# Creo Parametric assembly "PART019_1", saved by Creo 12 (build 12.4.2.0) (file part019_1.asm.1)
Units: Custom; MM, KILOGRAM, SECS

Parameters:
  PTC_WM_ITERATION = "0"
  PTC_WM_VERSION = "-.0"
  PTC_WM_LIFECYCLE_STATE = "In Work"
  PTC_WM_LIFECYCLE = "MO_CADDocument"
  PTC_WM_CREATED_BY = "Maximilian Roepper (Z0017RMS: MO)"
  PTC_WM_CREATED_ON = "18-Sep-26 11:36:42 AM"
  PTC_WM_MODIFIED_BY = "Maximilian Roepper (Z0017RMS: MO)"
  PTC_WM_MODIFIED_ON = "18-Sep-26 11:36:46 AM"
  PDMLINKNUMBER = "PDM000071455278"
  PTC_WM_NUMBER = "PDM000071455278"

Other parameters: WEIGHT, WEIGHT_FACTOR, WEIGHT_ADD, MC_ERRORS, SUPPLIER

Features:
  1. coordinate system
  2. imported feature
  3. component "SHAPESTRING268_1"

Other named items: DRW_VIEW_ORG, ROUGH-GROB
